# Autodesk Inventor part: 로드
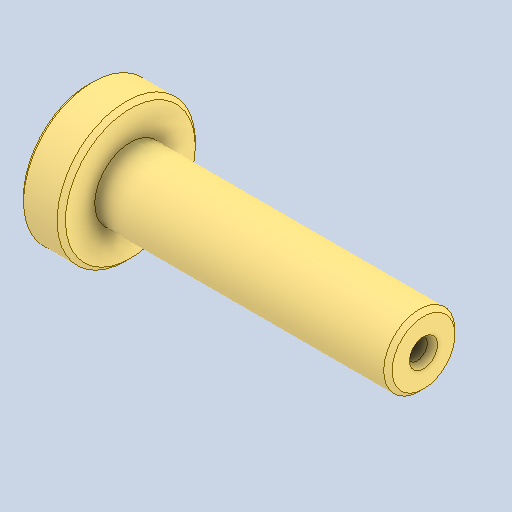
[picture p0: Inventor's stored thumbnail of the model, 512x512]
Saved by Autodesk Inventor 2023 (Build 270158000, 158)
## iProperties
Created: 2024-09
Part Number: 로드
Material: 강철, 탄소
Document SubType Name: Modeling
Designer: asung
Density: 7.85 g/cm^3
Appearance: 기본값
Author: jhkim
Sending System: Autodesk Inventor 2025
Preprocessor: ST-DEVELOPER v20
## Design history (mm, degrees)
feature "솔리드1"
node "솔리드2"
